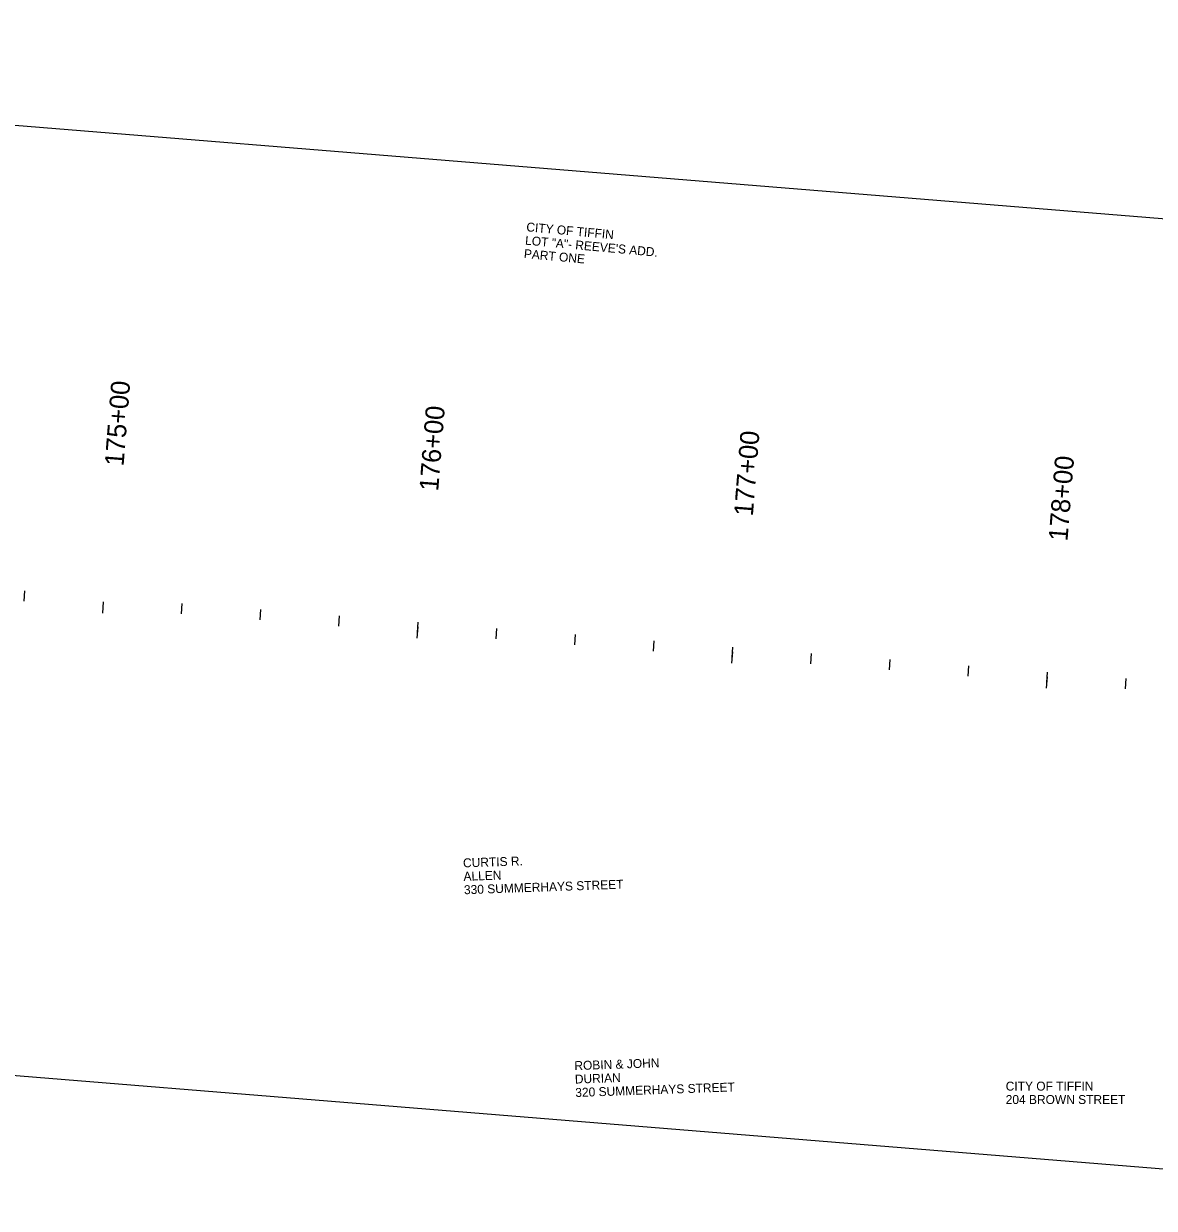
# Model space of a CAD drawing. Extents: x 20499788 to 20505371, y 7953467 to 7954209.
# Drawn here: x 20501185.4 to 20501543.6, y 7953750 to 7954125.3 of the extents above; entities that cross this region are included whole.
import ezdxf

# ---------------------------------------------------------------- set-up
doc = ezdxf.new("R2010")
doc.units = 0
for name, color, linetype in [('NamedBoundary', 7, 'Continuous'), ('Text', 7, 'Continuous'), ('TextAlignmentLrg', 7, 'Continuous'), ('TextAlignmentSml', 7, 'Continuous')]:
    doc.layers.add(name, color=color, linetype=linetype)

msp = doc.modelspace()

# ---------------------------------------------------------------- linework, layer by layer
at = {"layer": 'NamedBoundary'}
msp.add_lwpolyline([(20500786.55, 7954125.26), (20500762.22, 7953826.25), (20501699.61, 7953749.96), (20501723.94, 7954048.98)], close=True, dxfattribs=at)
at = {"layer": 'TextAlignmentLrg'}
for p, q in [((20501210.59, 7953942.14), (20501210.3, 7953938.48)), ((20501310.13, 7953932.39), (20501310.39, 7953935.66)), ((20501409.81, 7953924.47), (20501410.07, 7953927.74)), ((20501509.5, 7953916.55), (20501509.76, 7953919.81))]:
    msp.add_line(p, q, dxfattribs=at)
at = {"layer": 'TextAlignmentSml'}
for p, q in [((20501185.52, 7953942.29), (20501185.78, 7953945.56)), ((20501210.59, 7953942.14), (20501210.3, 7953938.48)), ((20501235.36, 7953938.33), (20501235.62, 7953941.6)), ((20501260.29, 7953936.35), (20501260.55, 7953939.62)), ((20501285.21, 7953934.37), (20501285.47, 7953937.64)), ((20501310.27, 7953934.22), (20501309.98, 7953930.56)), ((20501335.05, 7953930.41), (20501335.31, 7953933.68)), ((20501359.97, 7953928.43), (20501360.23, 7953931.7)), ((20501384.89, 7953926.45), (20501385.15, 7953929.72)), ((20501409.96, 7953926.3), (20501409.67, 7953922.64)), ((20501434.74, 7953922.49), (20501435, 7953925.76)), ((20501459.66, 7953920.51), (20501459.92, 7953923.78)), ((20501484.58, 7953918.53), (20501484.84, 7953921.79)), ((20501509.65, 7953918.38), (20501509.35, 7953914.72)), ((20501534.42, 7953914.57), (20501534.68, 7953917.83))]:
    msp.add_line(p, q, dxfattribs=at)

# ---------------------------------------------------------------- texts
at = {"layer": 'Text'}
for s, height, rotation, p in [('CITY OF TIFFIN', 2.8346, 354.7645, (20501344.53, 7954059.51)), ('LOT "A"- REEVE\'S ADD.', 2.8346, 354.7645, (20501344.14, 7954055.27)), ('PART ONE', 2.835, 354.7645, (20501343.75, 7954051.04)), ('CURTIS R.', 2.835, 2.0248, (20501324.61, 7953857.95)), ('ALLEN', 2.835, 2.0248, (20501324.76, 7953853.7)), ('330 SUMMERHAYS STREET', 2.8346, 2.0248, (20501324.91, 7953849.45)), ('ROBIN & JOHN', 2.8346, 2.0248, (20501359.89, 7953793.72)), ('DURIAN', 2.835, 2.0248, (20501360.04, 7953789.47)), ('320 SUMMERHAYS STREET', 2.8346, 2.0248, (20501360.19, 7953785.22))]:
    msp.add_text(s, height=height, rotation=rotation, dxfattribs=at).set_placement(p)
for s, p in [('CITY OF TIFFIN', (20501496.5, 7953787.26)), ('204 BROWN STREET', (20501496.5, 7953783.01))]:
    msp.add_text(s, height=2.8346, dxfattribs=at).set_placement(p)
at = {"layer": 'TextAlignmentLrg'}
msp.add_text('175+00', height=6.012, rotation=85.4564, dxfattribs=at).set_placement((20501217, 7953984.93))
at = {"layer": 'TextAlignmentSml'}
for s, p in [('175+00', (20501217, 7953984.93)), ('176+00', (20501316.69, 7953977.01)), ('177+00', (20501416.38, 7953969.09)), ('178+00', (20501516.06, 7953961.17))]:
    msp.add_text(s, height=6.012, rotation=85.4564, dxfattribs=at).set_placement(p)

doc.saveas('drawing.dxf')
